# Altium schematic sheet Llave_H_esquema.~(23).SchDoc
size A4
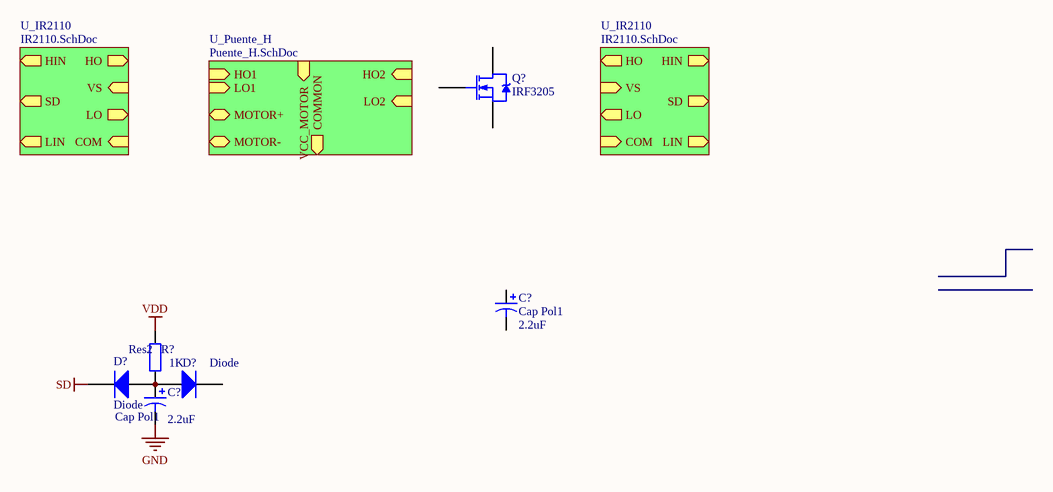
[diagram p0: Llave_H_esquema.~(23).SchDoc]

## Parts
(Parts that share a designator on the sheet are numbered #1, #2 ... from top to bottom, then left to right.)
C?#1  Cap Pol1  value 2.2uF  [RB7.6-15]
C?#2  Cap Pol1  value 2.2uF  [RB7.6-15]
D?#1  Diode  [SMC]
D?#2  Diode  [SMC]
Q?  IRF3205  [TO-220AB]
R?  Res2  value 1K  [AXIAL-0.4]

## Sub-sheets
U_IR2110 = IR2110.SchDoc: SD (out), HIN (out), LIN (out), HO (out), LO (out), VS (in), COM (in)
U_IR2110 = IR2110.SchDoc: SD (out), HIN (out), LIN (out), HO (out), LO (out), VS (in), COM (in)
U_Puente_H = Puente_H.SchDoc: HO1 (in), LO1 (in), HO2 (in), LO2 (in), MOTOR+ (bidir), MOTOR- (bidir), VCC_MOTOR (in), COMMON (out)

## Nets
GND: C?#2.2
SD: D?#2.2(K)
VDD: R?.2
NetC?#2_1: C?#2.1 D?#1.1(A) D?#2.1(A) R?.1

Not connected (* = marked no-connect by the designer): C?#1 1 2; D?#1 2(K); Q? 1(G) 2(D) 3(S)

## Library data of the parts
C?#1 C?#2 = Cap Pol1: Polarized Capacitor (Radial)
D?#1 D?#2 = Diode: Default Diode
Q? = IRF3205: HEXFET Power MOSFET; Note: Pin 2 is electrically connected to pin 4.
R? = Res2: Resistor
